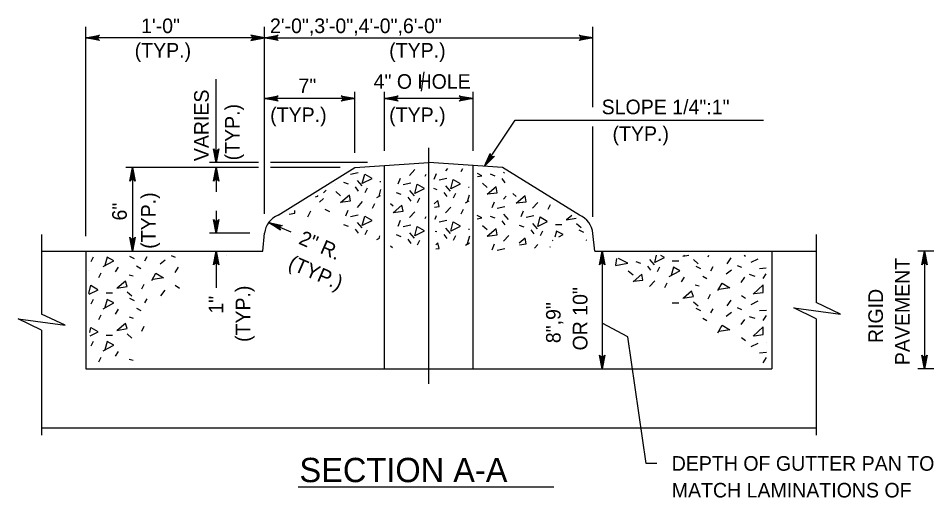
# Model space of a CAD drawing. Extents: x -7.6 to -0.4, y 98.1 to 108.3.
# Drawn here: x -7.43 to -3.67, y 106.378 to 108.349 of the extents above; entities that cross this region are included whole.
import ezdxf

# ---------------------------------------------------------------- set-up
doc = ezdxf.new("R2010")
doc.units = 0
for name, color, linetype in [('DETL-DIMS', 7, 'Continuous'), ('DETL-LINE', 7, 'Continuous'), ('DETL-NOTE', 7, 'Continuous'), ('DETL-PATT', 7, 'Continuous'), ('DETL-TITL', 7, 'Continuous')]:
    doc.layers.add(name, color=color, linetype=linetype)

msp = doc.modelspace()

# ---------------------------------------------------------------- linework, layer by layer
at = {"layer": 'DETL-DIMS'}
for p, q in [((-7.153, 107.4531), (-7.153, 108.3142)), ((-6.4185, 107.5447), (-6.4185, 108.3142)), ((-5.0695, 107.9838), (-5.0695, 108.3142)), ((-6.4185, 108.2691), (-7.153, 108.2691)), ((-6.4185, 108.2691), (-5.0695, 108.2691)), ((-6.6175, 107.7561), (-6.6175, 108.0992)), ((-6.0471, 107.7965), (-6.0471, 108.0469)), ((-5.9259, 107.8046), (-5.9259, 108.0469)), ((-5.5622, 107.8046), (-5.5622, 108.0469)), ((-6.0471, 108.0197), (-6.4185, 108.0197)), ((-5.5622, 108.0197), (-5.9259, 108.0197)), ((-5.5148, 107.7408), (-5.3889, 107.9298)), ((-5.3889, 107.9298), (-4.3696, 107.9298)), ((-5.0695, 107.5327), (-5.0695, 107.9038)), ((-5.744, 106.847), (-5.744, 107.8167)), ((-6.4437, 107.7359), (-6.9882, 107.7359)), ((-6.9609, 107.7359), (-6.9609, 107.3925)), ((-6.4437, 107.7561), (-6.6448, 107.7561)), ((-6.6175, 107.7359), (-6.6175, 107.6361)), ((-5.9953, 107.7561), (-6.3942, 107.7561)), ((-6.1077, 107.7359), (-6.3942, 107.7359)), ((-6.6175, 107.5573), (-6.6175, 107.4653)), ((-6.4016, 107.5096), (-6.3101, 107.4715)), ((-5.7191, 107.5225), (-5.7191, 107.5225)), ((-5.7191, 107.5225), (-5.7191, 107.5225)), ((-6.4791, 107.4653), (-6.6448, 107.4653)), ((-6.6175, 107.3925), (-6.6175, 107.2418)), ((-5.0317, 107.3925), (-5.0317, 106.9076)), ((-3.67, 107.3925), (-3.7351, 107.3925)), ((-3.7078, 107.3925), (-3.7078, 106.9076)), ((-6.5754, 107.3752), (-6.5754, 107.3752)), ((-6.5754, 107.3752), (-6.5754, 107.3752)), ((-3.67, 106.9076), (-3.7351, 106.9076)), ((-4.8067, 106.5193), (-4.8509, 106.5193))]:
    msp.add_line(p, q, dxfattribs=at)
for points in [[(-7.153, 108.2691), (-7.0965, 108.2797), (-7.1009, 108.2767), (-7.1031, 108.2729), (-7.1038, 108.2691), (-7.1031, 108.2653), (-7.1009, 108.2615), (-7.0965, 108.2585), (-7.153, 108.2691), (-7.1009, 108.2615), (-7.1031, 108.2653), (-7.153, 108.2691), (-7.1038, 108.2691), (-7.1031, 108.2729), (-7.153, 108.2691), (-7.1009, 108.2767)], [(-6.4185, 108.2691), (-6.475, 108.2797), (-6.4706, 108.2767), (-6.4684, 108.2729), (-6.4677, 108.2691), (-6.4684, 108.2653), (-6.4706, 108.2615), (-6.475, 108.2585), (-6.4185, 108.2691), (-6.4706, 108.2615), (-6.4684, 108.2653), (-6.4185, 108.2691), (-6.4677, 108.2691), (-6.4684, 108.2729), (-6.4185, 108.2691), (-6.4706, 108.2767)], [(-6.4185, 108.2691), (-6.362, 108.2797), (-6.3663, 108.2767), (-6.3686, 108.2729), (-6.3692, 108.2691), (-6.3686, 108.2653), (-6.3663, 108.2615), (-6.362, 108.2585), (-6.4185, 108.2691), (-6.3663, 108.2615), (-6.3686, 108.2653), (-6.4185, 108.2691), (-6.3692, 108.2691), (-6.3686, 108.2729), (-6.4185, 108.2691), (-6.3663, 108.2767)], [(-5.0695, 108.2691), (-5.126, 108.2585), (-5.1217, 108.2615), (-5.1194, 108.2653), (-5.1188, 108.2691), (-5.1194, 108.2729), (-5.1217, 108.2767), (-5.126, 108.2797), (-5.0695, 108.2691), (-5.1217, 108.2767), (-5.1194, 108.2729), (-5.0695, 108.2691), (-5.1188, 108.2691), (-5.1194, 108.2653), (-5.0695, 108.2691), (-5.1217, 108.2615)], [(-6.4185, 108.0197), (-6.362, 108.0303), (-6.3663, 108.0273), (-6.3686, 108.0235), (-6.3692, 108.0197), (-6.3686, 108.0159), (-6.3663, 108.0121), (-6.362, 108.0091), (-6.4185, 108.0197), (-6.3663, 108.0121), (-6.3686, 108.0159), (-6.4185, 108.0197), (-6.3692, 108.0197), (-6.3686, 108.0235), (-6.4185, 108.0197), (-6.3663, 108.0273)], [(-6.0471, 108.0197), (-6.1036, 108.0091), (-6.0992, 108.0121), (-6.097, 108.0159), (-6.0963, 108.0197), (-6.097, 108.0235), (-6.0992, 108.0273), (-6.1036, 108.0303), (-6.0471, 108.0197), (-6.0992, 108.0273), (-6.097, 108.0235), (-6.0471, 108.0197), (-6.0963, 108.0197), (-6.097, 108.0159), (-6.0471, 108.0197), (-6.0992, 108.0121)], [(-5.9259, 108.0197), (-5.8694, 108.0303), (-5.8737, 108.0273), (-5.876, 108.0235), (-5.8766, 108.0197), (-5.876, 108.0159), (-5.8737, 108.0121), (-5.8694, 108.0091), (-5.9259, 108.0197), (-5.8737, 108.0121), (-5.876, 108.0159), (-5.9259, 108.0197), (-5.8766, 108.0197), (-5.876, 108.0235), (-5.9259, 108.0197), (-5.8737, 108.0273)], [(-5.5622, 108.0197), (-5.6187, 108.0091), (-5.6144, 108.0121), (-5.6121, 108.0159), (-5.6115, 108.0197), (-5.6121, 108.0235), (-5.6144, 108.0273), (-5.6187, 108.0303), (-5.5622, 108.0197), (-5.6144, 108.0273), (-5.6121, 108.0235), (-5.5622, 108.0197), (-5.6115, 108.0197), (-5.6121, 108.0159), (-5.5622, 108.0197), (-5.6144, 108.0121)], [(-6.6175, 107.7561), (-6.6281, 107.8126), (-6.6251, 107.8083), (-6.6213, 107.806), (-6.6175, 107.8054), (-6.6137, 107.806), (-6.6099, 107.8083), (-6.6069, 107.8126), (-6.6175, 107.7561), (-6.6099, 107.8083), (-6.6137, 107.806), (-6.6175, 107.7561), (-6.6175, 107.8054), (-6.6213, 107.806), (-6.6175, 107.7561), (-6.6251, 107.8083)], [(-5.5148, 107.7408), (-5.4923, 107.7937), (-5.4922, 107.7884), (-5.4903, 107.7845), (-5.4875, 107.7818), (-5.484, 107.7803), (-5.4795, 107.78), (-5.4746, 107.782), (-5.5148, 107.7408), (-5.4795, 107.78), (-5.484, 107.7803), (-5.5148, 107.7408), (-5.4875, 107.7818), (-5.4903, 107.7845), (-5.5148, 107.7408), (-5.4922, 107.7884)], [(-6.9609, 107.7359), (-6.9503, 107.6794), (-6.9533, 107.6838), (-6.9571, 107.686), (-6.9609, 107.6867), (-6.9647, 107.686), (-6.9685, 107.6838), (-6.9715, 107.6794), (-6.9609, 107.7359), (-6.9685, 107.6838), (-6.9647, 107.686), (-6.9609, 107.7359), (-6.9609, 107.6867), (-6.9571, 107.686), (-6.9609, 107.7359), (-6.9533, 107.6838)], [(-6.6175, 107.7359), (-6.6069, 107.6794), (-6.6099, 107.6838), (-6.6137, 107.686), (-6.6175, 107.6867), (-6.6213, 107.686), (-6.6251, 107.6838), (-6.6281, 107.6794), (-6.6175, 107.7359), (-6.6251, 107.6838), (-6.6213, 107.686), (-6.6175, 107.7359), (-6.6175, 107.6867), (-6.6137, 107.686), (-6.6175, 107.7359), (-6.6099, 107.6838)], [(-6.6175, 107.4653), (-6.6281, 107.5218), (-6.6251, 107.5174), (-6.6213, 107.5152), (-6.6175, 107.5145), (-6.6137, 107.5152), (-6.6099, 107.5174), (-6.6069, 107.5218), (-6.6175, 107.4653), (-6.6099, 107.5174), (-6.6137, 107.5152), (-6.6175, 107.4653), (-6.6175, 107.5145), (-6.6213, 107.5152), (-6.6175, 107.4653), (-6.6251, 107.5174)], [(-6.4016, 107.5096), (-6.3454, 107.4977), (-6.3506, 107.4966), (-6.3541, 107.4939), (-6.3562, 107.4907), (-6.357, 107.4869), (-6.3564, 107.4826), (-6.3535, 107.4781), (-6.4016, 107.5096), (-6.3564, 107.4826), (-6.357, 107.4869), (-6.4016, 107.5096), (-6.3562, 107.4907), (-6.3541, 107.4939), (-6.4016, 107.5096), (-6.3506, 107.4966)], [(-6.9609, 107.3925), (-6.9715, 107.449), (-6.9685, 107.4446), (-6.9647, 107.4424), (-6.9609, 107.4417), (-6.9571, 107.4424), (-6.9533, 107.4446), (-6.9503, 107.449), (-6.9609, 107.3925), (-6.9533, 107.4446), (-6.9571, 107.4424), (-6.9609, 107.3925), (-6.9609, 107.4417), (-6.9647, 107.4424), (-6.9609, 107.3925), (-6.9685, 107.4446)], [(-6.6175, 107.3925), (-6.6069, 107.336), (-6.6099, 107.3404), (-6.6137, 107.3426), (-6.6175, 107.3433), (-6.6213, 107.3426), (-6.6251, 107.3404), (-6.6281, 107.336), (-6.6175, 107.3925), (-6.6251, 107.3404), (-6.6213, 107.3426), (-6.6175, 107.3925), (-6.6175, 107.3433), (-6.6137, 107.3426), (-6.6175, 107.3925), (-6.6099, 107.3404)], [(-5.0317, 107.3925), (-5.0211, 107.336), (-5.0241, 107.3404), (-5.0279, 107.3426), (-5.0317, 107.3433), (-5.0355, 107.3426), (-5.0392, 107.3404), (-5.0423, 107.336), (-5.0317, 107.3925), (-5.0392, 107.3404), (-5.0355, 107.3426), (-5.0317, 107.3925), (-5.0317, 107.3433), (-5.0279, 107.3426), (-5.0317, 107.3925), (-5.0241, 107.3404)], [(-3.7078, 107.3925), (-3.6972, 107.336), (-3.7002, 107.3404), (-3.704, 107.3426), (-3.7078, 107.3433), (-3.7116, 107.3426), (-3.7154, 107.3404), (-3.7184, 107.336), (-3.7078, 107.3925), (-3.7154, 107.3404), (-3.7116, 107.3426), (-3.7078, 107.3925), (-3.7078, 107.3433), (-3.704, 107.3426), (-3.7078, 107.3925), (-3.7002, 107.3404)], [(-4.8509, 106.5193), (-4.926, 107.0397), (-5.0317, 107.0957)], [(-5.0317, 106.9076), (-5.0423, 106.9641), (-5.0392, 106.9598), (-5.0355, 106.9575), (-5.0317, 106.9569), (-5.0279, 106.9575), (-5.0241, 106.9598), (-5.0211, 106.9641), (-5.0317, 106.9076), (-5.0241, 106.9598), (-5.0279, 106.9575), (-5.0317, 106.9076), (-5.0317, 106.9569), (-5.0355, 106.9575), (-5.0317, 106.9076), (-5.0392, 106.9598)], [(-3.7078, 106.9076), (-3.7184, 106.9641), (-3.7154, 106.9598), (-3.7116, 106.9575), (-3.7078, 106.9569), (-3.704, 106.9575), (-3.7002, 106.9598), (-3.6972, 106.9641), (-3.7078, 106.9076), (-3.7002, 106.9598), (-3.704, 106.9575), (-3.7078, 106.9076), (-3.7078, 106.9569), (-3.7116, 106.9575), (-3.7078, 106.9076), (-3.7154, 106.9598)]]:
    msp.add_lwpolyline(points, dxfattribs=at)
at = {"layer": 'DETL-LINE'}
for p, q in [((-6.3625, 107.5404), (-6.0471, 107.7359)), ((-6.0471, 107.7359), (-5.744, 107.7561)), ((-5.9259, 107.208), (-5.9259, 107.744)), ((-5.441, 107.7359), (-5.744, 107.7561)), ((-5.5622, 106.9076), (-5.5622, 107.744)), ((-5.1254, 107.5396), (-5.441, 107.7359)), ((-7.3349, 107.4608), (-7.3349, 107.1332)), ((-6.4258, 107.3925), (-6.4185, 107.4653)), ((-5.0623, 107.3925), (-5.0695, 107.4645)), ((-4.1532, 107.4608), (-4.1532, 107.1804)), ((-7.3349, 107.3925), (-6.4258, 107.3925)), ((-7.153, 107.3925), (-7.153, 106.9076)), ((-5.0623, 107.3925), (-4.1532, 107.3925)), ((-4.335, 107.3925), (-4.335, 106.9076)), ((-5.9259, 106.9076), (-5.9259, 107.208)), ((-4.1532, 107.1138), (-4.1532, 106.6353)), ((-7.3349, 107.0666), (-7.3349, 106.6353)), ((-7.153, 106.9076), (-4.335, 106.9076)), ((-7.3349, 106.6652), (-4.1532, 106.6652))]:
    msp.add_line(p, q, dxfattribs=at)
for points in [[(-4.1532, 107.1138), (-4.2451, 107.1588), (-4.0529, 107.1326), (-4.1532, 107.1804)], [(-7.3349, 107.0666), (-7.43, 107.1131), (-7.2378, 107.087), (-7.3349, 107.1332)]]:
    msp.add_lwpolyline(points, dxfattribs=at)
for centre, start, end in [((-6.328, 107.4562), 112.2917, 174.2894), ((-5.16, 107.4555), 5.7107, 67.6341)]:
    msp.add_arc(centre, 0.0909, start, end, dxfattribs=at)
at = {"layer": 'DETL-NOTE'}
msp.add_line((-5.7738, 108.0499), (-5.7635, 108.1288), dxfattribs=at)
at = {"layer": 'DETL-PATT'}
for p, q in [((-5.8012, 107.7272), (-5.8229, 107.7031)), ((-5.6664, 107.7318), (-5.6748, 107.7225)), ((-5.6058, 107.7305), (-5.6122, 107.7177)), ((-6.0338, 107.7137), (-6.065, 107.7065)), ((-5.8614, 107.6911), (-5.871, 107.667)), ((-5.7561, 107.7066), (-5.7603, 107.6983)), ((-5.7133, 107.7104), (-5.7229, 107.6864)), ((-5.67, 107.6912), (-5.7013, 107.6839)), ((-5.4919, 107.7093), (-5.4726, 107.7021)), ((-5.4438, 107.6901), (-5.4317, 107.6732)), ((-5.4365, 107.7166), (-5.4336, 107.7133)), ((-6.0939, 107.6752), (-6.0747, 107.668)), ((-6.0458, 107.6559), (-6.0338, 107.6391)), ((-6.0386, 107.6824), (-6.0193, 107.6608)), ((-5.9977, 107.6511), (-6.0073, 107.6319)), ((-5.9447, 107.6776), (-5.9408, 107.6776)), ((-5.818, 107.6718), (-5.8493, 107.6646)), ((-5.724, 107.6504), (-5.7109, 107.6454)), ((-5.6748, 107.6599), (-5.6555, 107.6382)), ((-5.5809, 107.6551), (-5.5783, 107.6551)), ((-5.5232, 107.6708), (-5.5039, 107.654)), ((-6.2087, 107.6151), (-6.2087, 107.6151)), ((-6.1758, 107.6319), (-6.1658, 107.6431)), ((-6.1252, 107.6367), (-6.106, 107.6198)), ((-5.9567, 107.6126), (-5.9422, 107.6207)), ((-5.9416, 107.6452), (-5.9495, 107.6174)), ((-5.8782, 107.6333), (-5.859, 107.6261)), ((-5.8301, 107.6141), (-5.818, 107.5972)), ((-5.8229, 107.6406), (-5.8036, 107.6189)), ((-5.682, 107.6334), (-5.67, 107.6166)), ((-5.6339, 107.6286), (-5.6435, 107.6093)), ((-5.578, 107.6218), (-5.5857, 107.5949)), ((-5.4257, 107.6179), (-5.4365, 107.6058)), ((-5.3982, 107.6283), (-5.3848, 107.6166)), ((-6.1926, 107.5934), (-6.1758, 107.6078)), ((-6.0169, 107.5958), (-6.0386, 107.5717)), ((-5.9664, 107.5862), (-5.976, 107.5669)), ((-5.901, 107.5874), (-5.8903, 107.578)), ((-5.7819, 107.6093), (-5.7916, 107.59)), ((-5.6531, 107.5732), (-5.6748, 107.5492)), ((-5.5929, 107.5901), (-5.5778, 107.5985)), ((-5.475, 107.5938), (-5.4847, 107.5697)), ((-5.4317, 107.5746), (-5.463, 107.5673)), ((-5.2957, 107.5926), (-5.3174, 107.5685)), ((-5.2452, 107.5829), (-5.2548, 107.5637)), ((-6.2408, 107.5332), (-6.2287, 107.5573)), ((-6.171, 107.5645), (-6.1517, 107.5549)), ((-6.0771, 107.5597), (-6.0867, 107.5356)), ((-6.0338, 107.5404), (-6.065, 107.5332)), ((-5.8012, 107.5539), (-5.8229, 107.5298)), ((-5.7133, 107.5371), (-5.7191, 107.5225)), ((-5.6026, 107.5636), (-5.6122, 107.5443)), ((-5.4919, 107.536), (-5.4726, 107.5288)), ((-5.4365, 107.5433), (-5.4177, 107.5221)), ((-5.3559, 107.5564), (-5.3655, 107.5324)), ((-5.3126, 107.5372), (-5.3439, 107.53)), ((-5.1569, 107.5383), (-5.1778, 107.5204)), ((-6.0939, 107.5019), (-6.0747, 107.4947)), ((-6.0386, 107.5091), (-6.0193, 107.4875)), ((-5.8614, 107.5178), (-5.871, 107.4937)), ((-5.818, 107.4986), (-5.8493, 107.4913)), ((-5.7561, 107.5333), (-5.7603, 107.525)), ((-5.67, 107.5179), (-5.7013, 107.5107)), ((-5.4438, 107.5168), (-5.4317, 107.4999)), ((-5.3728, 107.4987), (-5.3535, 107.4915)), ((-5.3174, 107.5059), (-5.2982, 107.4843)), ((-5.2235, 107.5011), (-5.1971, 107.5011)), ((-5.1802, 107.5204), (-5.1383, 107.5273)), ((-5.1369, 107.5059), (-5.1176, 107.4891)), ((-6.0458, 107.4827), (-6.0338, 107.4658)), ((-5.9977, 107.4778), (-6.0073, 107.4586)), ((-5.8229, 107.4673), (-5.8036, 107.4456)), ((-5.7173, 107.4746), (-5.7109, 107.4721)), ((-5.6748, 107.4866), (-5.6555, 107.4649)), ((-5.5809, 107.4818), (-5.5767, 107.4818)), ((-5.5232, 107.4975), (-5.5039, 107.4807)), ((-5.3246, 107.4794), (-5.3126, 107.4626)), ((-5.2765, 107.4746), (-5.2861, 107.4554)), ((-5.1273, 107.4794), (-5.108, 107.4698)), ((-5.9567, 107.4393), (-5.9468, 107.4448)), ((-5.9466, 107.4545), (-5.9495, 107.4442)), ((-5.8782, 107.46), (-5.859, 107.4528)), ((-5.8301, 107.4408), (-5.818, 107.4239)), ((-5.7819, 107.436), (-5.7916, 107.4167)), ((-5.682, 107.4601), (-5.67, 107.4433)), ((-5.6339, 107.4553), (-5.6435, 107.436)), ((-5.5929, 107.4168), (-5.5762, 107.4261)), ((-5.5764, 107.4541), (-5.5857, 107.4216)), ((-5.4149, 107.4566), (-5.4365, 107.4325)), ((-5.2356, 107.4361), (-5.2332, 107.4374)), ((-5.0984, 107.4385), (-5.0966, 107.4375)), ((-5.901, 107.4141), (-5.8925, 107.4066)), ((-5.475, 107.4205), (-5.4847, 107.3964)), ((-5.4317, 107.4013), (-5.463, 107.394)), ((-5.2957, 107.4193), (-5.3092, 107.4043)), ((-5.2452, 107.4096), (-5.2463, 107.4073)), ((-7.1222, 107.367), (-7.1318, 107.3478)), ((-6.9729, 107.3718), (-6.9537, 107.3622)), ((-6.9104, 107.3526), (-6.9007, 107.3694)), ((-6.8261, 107.355), (-6.8478, 107.3381)), ((-6.802, 107.3742), (-6.7852, 107.367)), ((-4.9725, 107.3619), (-4.9772, 107.3337)), ((-4.893, 107.3499), (-4.8738, 107.3426)), ((-4.8377, 107.3571), (-4.8184, 107.3354)), ((-4.7927, 107.3755), (-4.7775, 107.3667)), ((-4.7438, 107.3523), (-4.7174, 107.3523)), ((-4.7005, 107.3715), (-4.6764, 107.3755)), ((-4.6934, 107.3755), (-4.6981, 107.3715)), ((-4.6572, 107.3571), (-4.6379, 107.3402)), ((-4.597, 107.3691), (-4.5938, 107.3755)), ((-4.5031, 107.3643), (-4.52, 107.3402)), ((-4.4486, 107.3755), (-4.443, 107.3715)), ((-4.3924, 107.3595), (-4.4213, 107.3451)), ((-7.1414, 107.3117), (-7.1423, 107.3106)), ((-7.0307, 107.3068), (-7.0187, 107.3261)), ((-6.944, 107.3309), (-6.9272, 107.3213)), ((-6.7732, 107.3261), (-6.7876, 107.3044)), ((-4.9243, 107.3113), (-4.9051, 107.2945)), ((-4.8449, 107.3306), (-4.8329, 107.3138)), ((-4.7968, 107.3258), (-4.8064, 107.3065)), ((-4.6475, 107.3306), (-4.6283, 107.321)), ((-4.585, 107.3113), (-4.5753, 107.3282)), ((-4.5007, 107.3138), (-4.5224, 107.2969)), ((-4.4767, 107.333), (-4.4598, 107.3258)), ((-4.3852, 107.321), (-4.3585, 107.3232)), ((-7.0909, 107.302), (-7.1005, 107.2828)), ((-6.9753, 107.2948), (-6.9585, 107.29)), ((-4.7053, 107.2656), (-4.6933, 107.2849)), ((-4.6187, 107.2897), (-4.6018, 107.2801)), ((-4.4478, 107.2849), (-4.4622, 107.2632)), ((-4.4285, 107.2969), (-4.4045, 107.2897)), ((-4.3708, 107.2801), (-4.3583, 107.2987)), ((-6.9224, 107.237), (-6.9128, 107.2563)), ((-6.7852, 107.2515), (-6.7684, 107.2394)), ((-4.816, 107.2704), (-4.8377, 107.2464)), ((-4.7655, 107.2608), (-4.7751, 107.2416)), ((-4.65, 107.2536), (-4.6331, 107.2488)), ((-7.1029, 107.2322), (-7.1402, 107.2136)), ((-7.0692, 107.2202), (-7.0427, 107.2202)), ((-6.9826, 107.225), (-6.9633, 107.2082)), ((-6.9729, 107.1985), (-6.9537, 107.1889)), ((-6.8285, 107.2322), (-6.8454, 107.2082)), ((-4.597, 107.1958), (-4.5874, 107.2151)), ((-4.4598, 107.2103), (-4.443, 107.1982)), ((-7.1222, 107.1937), (-7.1318, 107.1744)), ((-6.9104, 107.1793), (-6.9007, 107.1961)), ((-4.7438, 107.179), (-4.7174, 107.179)), ((-4.6572, 107.1838), (-4.6379, 107.1669)), ((-4.5031, 107.191), (-4.52, 107.1669)), ((-4.4767, 107.1597), (-4.4598, 107.1525)), ((-4.3924, 107.1862), (-4.4213, 107.1717)), ((-7.0909, 107.1287), (-7.1005, 107.1095)), ((-7.0307, 107.1335), (-7.0187, 107.1528)), ((-6.944, 107.1576), (-6.9272, 107.148)), ((-4.6475, 107.1573), (-4.6283, 107.1477)), ((-4.585, 107.1381), (-4.5753, 107.1549)), ((-4.5007, 107.1404), (-4.5224, 107.1236)), ((-4.4285, 107.1236), (-4.4045, 107.1164)), ((-4.3852, 107.1477), (-4.3572, 107.15)), ((-4.3708, 107.1068), (-4.3571, 107.1273)), ((-6.9753, 107.1215), (-6.9585, 107.1167)), ((-4.6187, 107.1164), (-4.6018, 107.1068)), ((-4.4478, 107.1116), (-4.4622, 107.0899)), ((-7.1029, 107.0589), (-7.1365, 107.0421)), ((-7.0692, 107.0469), (-7.0427, 107.0469)), ((-6.9826, 107.0517), (-6.9633, 107.0349)), ((-6.9224, 107.0637), (-6.9128, 107.083)), ((-7.1222, 107.0204), (-7.1318, 107.0012)), ((-4.4598, 107.037), (-4.443, 107.0249)), ((-4.3924, 107.0129), (-4.4213, 106.9984)), ((-4.3563, 107.0177), (-4.3563, 107.0177)), ((-7.0307, 106.9602), (-7.0187, 106.9795)), ((-4.3852, 106.9744), (-4.3563, 106.9768)), ((-7.0909, 106.9554), (-7.1005, 106.9362)), ((-6.9753, 106.9482), (-6.9585, 106.9434)), ((-4.3708, 106.9335), (-4.3563, 106.9551))]:
    msp.add_line(p, q, dxfattribs=at)
for points in [[(-5.9784, 107.6897), (-6.0169, 107.6704), (-6.0073, 107.7089), (-5.9784, 107.6921)], [(-5.6146, 107.6671), (-5.6531, 107.6478), (-5.6435, 107.6864), (-5.6146, 107.6695)], [(-5.5438, 107.6986), (-5.5256, 107.7021), (-5.5437, 107.7112)], [(-6.1277, 107.668), (-6.1276, 107.668), (-6.1277, 107.668)], [(-5.7627, 107.6478), (-5.8012, 107.6285), (-5.7916, 107.667), (-5.7627, 107.6502)], [(-5.5039, 107.6275), (-5.463, 107.6323), (-5.4678, 107.6564), (-5.5039, 107.6251)], [(-6.2087, 107.6151), (-6.1998, 107.6174), (-6.2002, 107.6207)], [(-6.106, 107.5934), (-6.065, 107.5982), (-6.0699, 107.6223), (-6.106, 107.591)], [(-5.3848, 107.5902), (-5.3439, 107.595), (-5.3487, 107.619), (-5.3848, 107.5877)], [(-5.8903, 107.5515), (-5.8493, 107.5563), (-5.8542, 107.5804), (-5.8903, 107.5491)], [(-5.7211, 107.5733), (-5.7013, 107.5756), (-5.7061, 107.5997), (-5.7216, 107.5863)], [(-6.3168, 107.5446), (-6.2937, 107.5476), (-6.2937, 107.5596)], [(-5.9784, 107.5164), (-6.0169, 107.4971), (-6.0073, 107.5356), (-5.9784, 107.5188)], [(-5.5452, 107.5251), (-5.5256, 107.5288), (-5.5451, 107.5386)], [(-5.6146, 107.4938), (-5.6531, 107.4746), (-5.6435, 107.5131), (-5.6146, 107.4962)], [(-5.2572, 107.5131), (-5.2957, 107.4939), (-5.2861, 107.5324), (-5.2572, 107.5155)], [(-5.7627, 107.4745), (-5.8012, 107.4552), (-5.7916, 107.4937), (-5.7627, 107.4769)], [(-5.5039, 107.4542), (-5.463, 107.459), (-5.4678, 107.4831), (-5.5039, 107.4518)], [(-5.2097, 107.4505), (-5.1923, 107.4602), (-5.2187, 107.4746), (-5.2258, 107.4498)], [(-5.7145, 107.4008), (-5.7013, 107.4023), (-5.7061, 107.4264), (-5.7152, 107.4185)], [(-5.3719, 107.4184), (-5.3439, 107.4217), (-5.3487, 107.4457), (-5.3727, 107.4249)], [(-7.0813, 107.3285), (-7.0379, 107.3526), (-7.0644, 107.367), (-7.074, 107.3333)], [(-4.9768, 107.3331), (-4.9268, 107.3426), (-4.9653, 107.3619)], [(-4.7775, 107.3643), (-4.816, 107.3451), (-4.8084, 107.3755)], [(-4.7559, 107.2873), (-4.7125, 107.3113), (-4.739, 107.3258), (-4.7486, 107.2921)], [(-6.8815, 107.2707), (-6.8646, 107.302), (-6.8333, 107.2828), (-6.8767, 107.2756)], [(-4.9051, 107.268), (-4.8642, 107.2728), (-4.869, 107.2969), (-4.9051, 107.2656)], [(-7.1403, 107.2174), (-7.1318, 107.2515), (-7.1029, 107.2346)], [(-7.0259, 107.2394), (-6.9826, 107.2467), (-6.9898, 107.2683), (-7.0235, 107.2394)], [(-4.5561, 107.2295), (-4.5392, 107.2608), (-4.5079, 107.2416), (-4.5513, 107.2343)], [(-4.4069, 107.2175), (-4.3708, 107.2223), (-4.3708, 107.2536), (-4.4117, 107.2151)], [(-4.7005, 107.1982), (-4.6572, 107.2054), (-4.6644, 107.2271), (-4.6981, 107.1982)], [(-7.0813, 107.1552), (-7.0379, 107.1793), (-7.0644, 107.1937), (-7.074, 107.16)], [(-7.0259, 107.0662), (-6.9826, 107.0734), (-6.9898, 107.095), (-7.0235, 107.0662)], [(-4.5561, 107.0562), (-4.5392, 107.0875), (-4.5079, 107.0683), (-4.5513, 107.061)], [(-7.1368, 107.058), (-7.1318, 107.0782), (-7.1029, 107.0613)], [(-4.4069, 107.0442), (-4.3708, 107.049), (-4.3708, 107.0803), (-4.4117, 107.0418)], [(-7.0813, 106.9819), (-7.0379, 107.006), (-7.0644, 107.0204), (-7.074, 106.9867)]]:
    msp.add_lwpolyline(points, dxfattribs=at)
at = {"layer": 'DETL-TITL'}
msp.add_line((-6.2802, 106.4237), (-5.23, 106.4237), dxfattribs=at)

# ---------------------------------------------------------------- texts
at = {"layer": 'DETL-NOTE'}
for s, p in [('1\'-0"', (-6.9257, 108.2883)), ('2\'-0",3\'-0",4\'-0",6\'-0"', (-6.3963, 108.2883)), ('(TYP.)', (-6.952, 108.1875)), ('(TYP.)', (-5.9066, 108.1875)), ('7"', (-6.2791, 108.0416)), ('4" O HOLE', (-5.9704, 108.0594)), ('SLOPE 1/4":1"', (-5.0338, 107.9548)), ('(TYP.)', (-6.3954, 107.9225)), ('(TYP.)', (-5.9066, 107.9225)), ('  (TYP.) ', (-5.0338, 107.8448)), ('DEPTH OF GUTTER PAN TO', (-4.746, 106.4893)), ('MATCH LAMINATIONS OF', (-4.746, 106.3793))]:
    msp.add_text(s, height=0.06, dxfattribs=at).set_placement(p)
for s, rotation, p in [('VARIES', 90, (-6.6477, 107.7619)), ('(TYP.)', 90, (-6.5212, 107.7651)), ('(TYP.)', 90, (-6.8658, 107.4016)), ('6"', 90, (-6.9843, 107.5179)), ('2" R.', 336.5852, (-6.2823, 107.4235)), ('(TYP.)', 336.5852, (-6.326, 107.3225)), ('PAVEMENT', 90, (-3.7684, 106.9233)), ('(TYP.)', 90, (-6.4775, 107.0186)), ('OR 10"', 90, (-5.0923, 106.9837)), ('1"', 90, (-6.5875, 107.1349)), ('RIGID', 90, (-3.8784, 107.0141)), ('8",9"', 90, (-5.2023, 107.0137))]:
    msp.add_text(s, height=0.06, rotation=rotation, dxfattribs=at).set_placement(p)
at = {"layer": 'DETL-TITL'}
msp.add_text('SECTION A-A', height=0.1, dxfattribs=at).set_placement((-6.2751, 106.4423))

doc.saveas('drawing.dxf')
